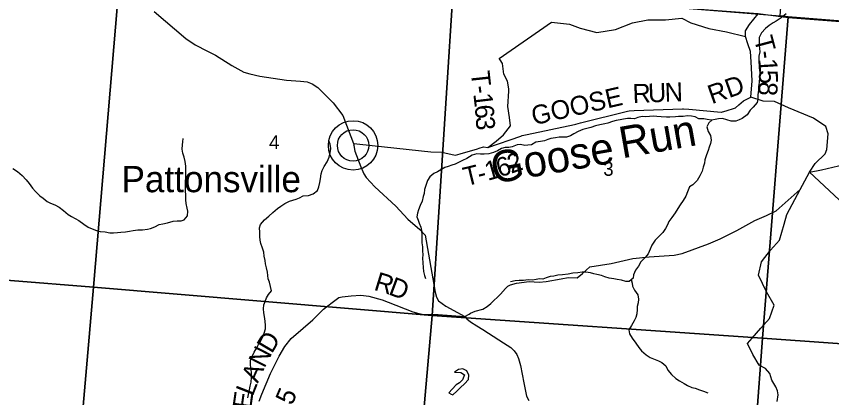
# Model space of a CAD drawing. Extents: x 0 to 42, y 0 to 22.
# Drawn here: x 6.349 to 7.577, y 19.536 to 20.11 of the extents above; entities that cross this region are included whole.
import ezdxf

# ---------------------------------------------------------------- set-up
doc = ezdxf.new("R2010")
doc.units = 0
for name, color, linetype in [('GM_X_County_Road', 7, 'Continuous'), ('GM_X_Minor_Lake', 7, 'Continuous'), ('GM_X_Minor_River', 7, 'Continuous'), ('GM_X_Minor_River_Text', 7, 'Continuous'), ('GM_X_Section', 7, 'Continuous'), ('GM_X_Section_Text', 7, 'Continuous'), ('GM_X_Township', 7, 'Continuous'), ('GM_X_Township_Road', 7, 'Continuous'), ('GM_X_Township_Road_Text', 7, 'Continuous'), ('GM_X_Unincorporated', 7, 'Continuous'), ('GM_X_Unincorporated_Location', 7, 'Continuous'), ('GM_X_Unincorporated_Text', 7, 'Continuous')]:
    doc.layers.add(name, color=color, linetype=linetype)

msp = doc.modelspace()

# ---------------------------------------------------------------- linework, layer by layer
at = {"layer": 'GM_X_County_Road'}
msp.add_lwpolyline([(6.5568, 20.1173), (6.6043, 20.0769), (6.6185, 20.0672), (6.6369, 20.0579), (6.6492, 20.0517), (6.6739, 20.0361), (6.6916, 20.026), (6.7009, 20.0236), (6.716, 20.0202), (6.7562, 20.0143), (6.777, 20.0127), (6.787, 20.0118), (6.7949, 20.0088), (6.8033, 20.003), (6.8264, 19.9801), (6.8408, 19.961), (6.8463, 19.9462), (6.857, 19.9189), (6.8591, 19.9075), (6.8678, 19.8837), (6.8727, 19.8731), (6.8759, 19.8674), (6.889, 19.8535), (6.9206, 19.8244), (6.9389, 19.8047), (6.9566, 19.7894), (6.9648, 19.7807), (6.9799, 19.6953), (6.9818, 19.6874), (6.9852, 19.6823), (6.996, 19.674), (7.0136, 19.6643), (7.0245, 19.6586), (7.0274, 19.6552), (7.0333, 19.6507), (7.0428, 19.6445), (7.0518, 19.6388), (7.06, 19.6334), (7.0828, 19.6187), (7.0938, 19.6118), (7.099, 19.6066), (7.1027, 19.6014), (7.1055, 19.5953), (7.1083, 19.585), (7.1133, 19.5587), (7.1177, 19.5388), (7.1212, 19.532)], dxfattribs=at)
at = {"layer": 'GM_X_Minor_Lake'}
for points in [[(7.0093, 19.5745), (7.0187, 19.5741), (7.024, 19.5705), (7.0211, 19.5631), (7.0164, 19.5589), (7.0115, 19.5557), (7.0056, 19.5489), (7.0003, 19.5436), (7.004, 19.5417)], [(7.004, 19.5417), (7.0063, 19.5406), (7.0124, 19.5462), (7.0183, 19.5515), (7.0242, 19.5574), (7.0299, 19.5638), (7.0306, 19.5704), (7.0278, 19.5767), (7.0214, 19.5797), (7.0151, 19.5786), (7.0093, 19.5745)]]:
    msp.add_lwpolyline(points, dxfattribs=at)
at = {"layer": 'GM_X_Minor_River'}
for points in [[(7.5084, 20.1138), (7.5012, 20.1078), (7.4936, 20.103), (7.4887, 20.1002), (7.483, 20.0962), (7.4775, 20.0919), (7.4714, 20.0853), (7.4678, 20.0783), (7.4676, 20.0734), (7.4679, 20.0667), (7.4685, 20.0616), (7.4688, 20.0569), (7.4675, 20.0502), (7.4675, 20.0434), (7.469, 20.0362), (7.4693, 20.0301), (7.4686, 20.0229), (7.4685, 20.018), (7.4676, 20.0108), (7.4666, 20.0044), (7.4666, 19.9989), (7.466, 19.992), (7.4656, 19.9854), (7.4648, 19.9805), (7.4589, 19.9735), (7.4542, 19.9688), (7.4496, 19.962), (7.4424, 19.9563), (7.4377, 19.9544), (7.4327, 19.9523), (7.4255, 19.9524), (7.4193, 19.9543), (7.4127, 19.9562), (7.4068, 19.956), (7.4017, 19.9549), (7.3962, 19.954), (7.3896, 19.9551), (7.3843, 19.9557), (7.3771, 19.9561), (7.3714, 19.959), (7.3661, 19.9601), (7.3601, 19.9603), (7.3535, 19.9594), (7.3466, 19.9592), (7.3417, 19.9587), (7.3334, 19.9583), (7.3285, 19.9583), (7.3201, 19.9587), (7.3139, 19.9595), (7.3082, 19.9597), (7.3029, 19.9592), (7.2967, 19.9588), (7.2916, 19.9592), (7.2853, 19.9577), (7.28, 19.956), (7.2747, 19.9564), (7.2694, 19.9566), (7.2635, 19.9553), (7.2586, 19.9546), (7.2527, 19.9532), (7.2471, 19.9517), (7.2402, 19.9493), (7.2355, 19.9482), (7.2281, 19.9469), (7.2215, 19.9452), (7.2143, 19.9431), (7.2084, 19.9414), (7.2023, 19.9397), (7.1953, 19.9369), (7.1889, 19.9332), (7.1838, 19.9303), (7.1777, 19.9283), (7.1718, 19.9283), (7.1667, 19.9281), (7.161, 19.9272), (7.1542, 19.9264), (7.1495, 19.9247), (7.1447, 19.9229), (7.1387, 19.9217), (7.1317, 19.9206), (7.1249, 19.917), (7.1197, 19.9163), (7.1148, 19.9159), (7.1084, 19.9171), (7.1035, 19.9169), (7.0961, 19.9137), (7.091, 19.9128), (7.0855, 19.9126)], [(7.3966, 19.954), (7.3922, 19.9498), (7.3892, 19.9439), (7.3911, 19.9371), (7.3944, 19.9307), (7.3956, 19.9238), (7.3946, 19.9189), (7.3927, 19.9134), (7.3908, 19.9085), (7.3887, 19.9017), (7.3862, 19.8941), (7.3854, 19.8894), (7.3833, 19.8831), (7.3818, 19.8774), (7.3787, 19.87), (7.3745, 19.863), (7.3679, 19.8568), (7.363, 19.8534), (7.3599, 19.846), (7.3576, 19.8396), (7.3536, 19.8332), (7.3489, 19.8265), (7.3454, 19.821), (7.3411, 19.8146), (7.3363, 19.8074), (7.3319, 19.8012), (7.3297, 19.7963), (7.327, 19.791), (7.3226, 19.7851), (7.3171, 19.7794), (7.3112, 19.7734), (7.3061, 19.766), (7.3036, 19.7596), (7.3009, 19.7529), (7.2968, 19.7476), (7.2895, 19.7405), (7.2859, 19.734), (7.2816, 19.728), (7.2787, 19.7212), (7.2779, 19.7164), (7.2722, 19.7113), (7.2671, 19.7113), (7.2605, 19.7131), (7.2541, 19.714), (7.249, 19.715), (7.242, 19.716), (7.2355, 19.7183), (7.2304, 19.7204), (7.2236, 19.7215), (7.2187, 19.7229), (7.2138, 19.7244), (7.207, 19.7252), (7.2015, 19.725), (7.1948, 19.7244), (7.1871, 19.7237), (7.1801, 19.7224), (7.1719, 19.7213), (7.1649, 19.7209), (7.1585, 19.7192), (7.153, 19.7185), (7.1473, 19.7168), (7.142, 19.7149), (7.1371, 19.7151), (7.1318, 19.7144), (7.1267, 19.7131), (7.1199, 19.7135), (7.1132, 19.7129), (7.1066, 19.7129), (7.1002, 19.712), (7.0932, 19.7107)], [(6.6046, 19.8339), (6.6043, 19.8411), (6.6039, 19.8477), (6.6039, 19.8534), (6.6041, 19.861), (6.6045, 19.868), (6.6044, 19.8727), (6.6044, 19.8801), (6.6046, 19.8849), (6.6033, 19.8917), (6.6018, 19.898), (6.5998, 19.9042), (6.599, 19.9105), (6.5992, 19.9167), (6.6002, 19.9215), (6.6006, 19.9262)], [(6.7893, 19.8406), (6.796, 19.8433), (6.8027, 19.8482), (6.8046, 19.8537), (6.8061, 19.8602), (6.8071, 19.8655), (6.8084, 19.8734), (6.8096, 19.8782), (6.8128, 19.8844), (6.8172, 19.8912), (6.8201, 19.898), (6.8218, 19.905), (6.8226, 19.9111), (6.8218, 19.9179), (6.8196, 19.9227)], [(7.0855, 19.9126), (7.0798, 19.9111), (7.0739, 19.9079), (7.0677, 19.9051), (7.0608, 19.9032), (7.0535, 19.9027), (7.0482, 19.9029), (7.0427, 19.9033), (7.0358, 19.9014), (7.0277, 19.8963), (7.0212, 19.8933), (7.0161, 19.8906), (7.0101, 19.8876), (7.0051, 19.8863), (6.9994, 19.8844), (6.9947, 19.8825), (6.9833, 19.8761), (6.978, 19.8735), (6.9721, 19.8688), (6.9685, 19.8631), (6.9657, 19.8557), (6.9638, 19.8495), (6.9632, 19.8438), (6.962, 19.8389), (6.9605, 19.8322), (6.9574, 19.8256), (6.9549, 19.8192), (6.9534, 19.814), (6.9525, 19.8087), (6.9545, 19.8036), (6.956, 19.7989), (6.9585, 19.793), (6.9594, 19.7877), (6.9597, 19.7809), (6.9599, 19.7744), (6.9601, 19.7691), (6.9608, 19.7632), (6.961, 19.7572), (6.9612, 19.7513), (6.961, 19.7464), (6.9621, 19.7321), (6.9626, 19.7263), (6.9637, 19.7204), (6.9656, 19.7156)], [(6.344, 19.8814), (6.351, 19.8768), (6.3578, 19.8707), (6.3642, 19.8641), (6.3684, 19.8587), (6.3736, 19.8515), (6.378, 19.8464), (6.3844, 19.8403), (6.3895, 19.8363), (6.3959, 19.8317), (6.4008, 19.8292), (6.407, 19.8264), (6.4138, 19.8228), (6.4203, 19.8178), (6.4272, 19.8121), (6.4323, 19.809), (6.438, 19.806), (6.4431, 19.8031), (6.451, 19.7976), (6.4576, 19.793), (6.4633, 19.7902), (6.4701, 19.7881), (6.4756, 19.7863), (6.483, 19.7857), (6.49, 19.7842), (6.4953, 19.7842), (6.5015, 19.7849), (6.5068, 19.7855), (6.5136, 19.786), (6.5195, 19.7871), (6.525, 19.7879), (6.5322, 19.7888), (6.5392, 19.7891), (6.5466, 19.7899), (6.5515, 19.791), (6.5577, 19.7933), (6.5642, 19.797), (6.5697, 19.7981), (6.5771, 19.7994), (6.5854, 19.8017), (6.5913, 19.8024), (6.5975, 19.8024), (6.6022, 19.8041), (6.607, 19.81), (6.6074, 19.8168), (6.6063, 19.8217), (6.6048, 19.8287), (6.6046, 19.8339)], [(6.6978, 19.5359), (6.6988, 19.5413), (6.7003, 19.5482), (6.7011, 19.5539), (6.7028, 19.5597), (6.7034, 19.5667), (6.7033, 19.5732), (6.7027, 19.5793), (6.7016, 19.5851), (6.702, 19.5922), (6.7047, 19.5995), (6.7073, 19.6048), (6.7115, 19.6115), (6.7138, 19.6164), (6.7178, 19.623), (6.7205, 19.6283), (6.7226, 19.6332), (6.7243, 19.6401), (6.7243, 19.6448), (6.724, 19.6514), (6.723, 19.6586), (6.7221, 19.6638), (6.7216, 19.67), (6.722, 19.6759), (6.7237, 19.681), (6.7258, 19.6867), (6.7292, 19.6918), (6.7336, 19.6971), (6.7321, 19.7037), (6.7304, 19.7102), (6.7283, 19.7153), (6.7278, 19.7204), (6.7274, 19.7254), (6.7259, 19.7316), (6.7246, 19.7379), (6.7239, 19.7426), (6.7224, 19.7493), (6.7217, 19.7555), (6.7198, 19.7614), (6.7174, 19.7684), (6.7166, 19.7732), (6.7161, 19.7789), (6.7157, 19.7855), (6.7156, 19.7918), (6.7171, 19.7971), (6.723, 19.8041), (6.7296, 19.8096), (6.7355, 19.8148), (6.7427, 19.8211), (6.7475, 19.8245), (6.7535, 19.8286), (6.7605, 19.8318), (6.7655, 19.8337), (6.7706, 19.835), (6.7757, 19.8371), (6.781, 19.8399), (6.7893, 19.8406)], [(7.2753, 19.7141), (7.2766, 19.7088), (7.2773, 19.7039), (7.2799, 19.698), (7.2852, 19.6912), (7.2861, 19.6846), (7.2854, 19.6789), (7.284, 19.6736), (7.2842, 19.6688), (7.2838, 19.6626), (7.2823, 19.6569), (7.2794, 19.6518), (7.2758, 19.645), (7.2718, 19.6385), (7.2724, 19.6323), (7.2767, 19.6258), (7.282, 19.6186), (7.2867, 19.6116), (7.2908, 19.6068), (7.2978, 19.6009), (7.3039, 19.5969), (7.3088, 19.5946), (7.3163, 19.5916), (7.3214, 19.5895), (7.3273, 19.584), (7.3301, 19.5775), (7.3356, 19.5712), (7.3424, 19.5654), (7.348, 19.5617), (7.3548, 19.5575), (7.3599, 19.5545), (7.3666, 19.5518), (7.3715, 19.5507), (7.3781, 19.548), (7.3839, 19.5459), (7.3906, 19.5434)]]:
    msp.add_lwpolyline(points, dxfattribs=at)
at = {"layer": 'GM_X_Section'}
for points in [[(7.5385, 20.6135), (8.0546, 20.576), (8.0131, 20.0691), (7.5113, 20.1095), (7.4997, 20.1108)], [(6.0085, 20.238), (6.4512, 20.1989), (6.5071, 20.1953), (6.4653, 19.7024), (5.9652, 19.7427)], [(6.5071, 20.1953), (6.9833, 20.1533), (7.0068, 20.151), (6.9755, 19.66), (6.4653, 19.7024)], [(7.4997, 20.1108), (7.5113, 20.1095), (7.4728, 19.6259), (6.9755, 19.66), (7.0068, 20.151)], [(7.5113, 20.1095), (8.0131, 20.0691), (8.0207, 20.0684), (7.9742, 19.5901), (7.4728, 19.6259)], [(5.9652, 19.7427), (6.4653, 19.7024), (6.4215, 19.1942), (5.9249, 19.2362)], [(6.4653, 19.7024), (6.9755, 19.66), (6.9308, 19.1519), (6.4215, 19.1942)], [(7.4728, 19.6259), (7.4347, 19.1125), (6.9308, 19.1519), (6.9755, 19.66)], [(7.4728, 19.6259), (7.9742, 19.5901), (7.9439, 19.075), (7.4347, 19.1125)]]:
    msp.add_lwpolyline(points, close=True, dxfattribs=at)
at = {"layer": 'GM_X_Township'}
msp.add_lwpolyline([(6.3062, 20.211), (6.4486, 20.1964), (6.4625, 20.1954), (6.5052, 20.1923), (6.9777, 20.151), (7.4661, 20.1144), (7.5116, 20.1083), (8.1585, 20.0585), (8.5294, 20.0335), (8.4853, 19.4313)], dxfattribs=at)
at = {"layer": 'GM_X_Township_Road'}
msp.add_lwpolyline([(8.604, 20.9), (5.4466, 20.9), (5.4327, 20.7492), (5.4317, 20.7371), (5.4312, 20.7306), (5.4298, 20.7203), (5.4281, 20.716), (5.4083, 20.5211), (5.3882, 20.287), (5.7544, 20.2607), (6.2569, 20.215), (6.3062, 20.211), (6.4486, 20.1964), (6.4625, 20.1954), (6.5052, 20.1923), (6.9777, 20.151), (7.4661, 20.1144), (7.5116, 20.1083), (8.1585, 20.0585), (8.5294, 20.0335), (8.5516, 20.2479), (8.5706, 20.4739), (8.6039, 20.8987)], close=True, dxfattribs=at)
for points in [[(7.4551, 19.9884), (7.4574, 20.013), (7.4557, 20.0418), (7.4548, 20.0572), (7.4506, 20.069), (7.4474, 20.0799), (7.4474, 20.0885), (7.4535, 20.0981), (7.4662, 20.1141), (7.4669, 20.1149)], [(7.0777, 20.0445), (7.0764, 20.0466), (7.1552, 20.1016), (7.1824, 20.0985), (7.1982, 20.0923), (7.2232, 20.086), (7.2515, 20.0902), (7.2771, 20.1006), (7.3, 20.1047), (7.327, 20.1047), (7.3512, 20.1075), (7.365, 20.1006), (7.392, 20.0916), (7.4187, 20.0866), (7.4474, 20.0799)], [(7.0909, 19.9974), (7.0911, 20.0009), (7.0887, 20.0126), (7.0835, 20.023), (7.0811, 20.0392), (7.0777, 20.0445)], [(7.059, 19.913), (7.0718, 19.9223), (7.0828, 19.9316), (7.0935, 19.9454), (7.0921, 19.9578), (7.0894, 19.9747), (7.0909, 19.9974)], [(7.0462, 19.9118), (7.0528, 19.9138), (7.059, 19.913), (7.1088, 19.93), (7.1107, 19.9306), (7.1183, 19.9322), (7.1896, 19.9476), (7.1918, 19.948), (7.199, 19.9498), (7.2698, 19.9674), (7.2722, 19.968), (7.2795, 19.9683), (7.3524, 19.9712), (7.3541, 19.9712), (7.362, 19.9705), (7.4105, 19.966), (7.4111, 19.9659), (7.4197, 19.9687), (7.429, 19.9717), (7.432, 19.9727), (7.437, 19.9769), (7.4445, 19.9831), (7.4551, 19.9884)], [(7.7314, 19.7005), (7.5437, 19.8759), (7.5523, 19.8886), (7.567, 19.903), (7.5696, 19.9099), (7.5716, 19.9332), (7.5681, 19.9444), (7.5498, 19.9571), (7.5122, 19.9723), (7.4909, 19.9819), (7.4737, 19.9824), (7.4551, 19.9884)], [(6.857, 19.9189), (6.8618, 19.9182), (6.9593, 19.908), (6.9735, 19.9065), (6.9901, 19.9057), (7.0055, 19.9021), (7.0106, 19.9013), (7.0174, 19.9033), (7.0435, 19.911), (7.0462, 19.9118)], [(7.2016, 19.7234), (7.2129, 19.7333), (7.2452, 19.7382), (7.2775, 19.7457), (7.3023, 19.7482), (7.3396, 19.7507), (7.352, 19.7531), (7.3917, 19.768), (7.4091, 19.7755), (7.434, 19.7879), (7.4613, 19.8028), (7.4787, 19.8103), (7.4936, 19.8177), (7.5297, 19.8497), (7.5437, 19.8759), (7.5619, 19.8792), (7.6043, 19.889)], [(7.4952, 19.5306), (7.4965, 19.5404), (7.4955, 19.5467), (7.4929, 19.5524), (7.487, 19.5629), (7.4841, 19.5726), (7.4774, 19.5802), (7.4677, 19.5851), (7.4581, 19.6012), (7.4505, 19.6178), (7.4575, 19.6258), (7.4704, 19.6407), (7.4833, 19.6556), (7.4905, 19.6756), (7.479, 19.6956), (7.4669, 19.7206), (7.4712, 19.7406), (7.4847, 19.7584), (7.4983, 19.7734), (7.5054, 19.7975), (7.5097, 19.8119), (7.5297, 19.8497)], [(7.031, 19.6622), (7.0332, 19.6635), (7.0403, 19.6663), (7.0516, 19.6696), (7.0582, 19.6734), (7.064, 19.6782), (7.0785, 19.6919), (7.0858, 19.7008), (7.0894, 19.7042), (7.0934, 19.7063), (7.1024, 19.7084), (7.1213, 19.7109), (7.1365, 19.7102), (7.147, 19.7113), (7.1695, 19.7152), (7.1802, 19.717), (7.1938, 19.7165), (7.2016, 19.7234)], [(6.715, 19.5311), (6.7187, 19.5417), (6.7321, 19.5729), (6.7452, 19.5989), (6.7535, 19.6135), (6.7633, 19.6256), (6.7812, 19.6407), (6.7959, 19.6535), (6.8118, 19.6695), (6.8247, 19.6793), (6.835, 19.6872), (6.84, 19.6883), (6.8534, 19.6896), (6.8678, 19.6905), (6.88, 19.6891), (6.9001, 19.6834), (6.9091, 19.6801), (6.9461, 19.6655), (6.9554, 19.6631), (6.9627, 19.6617), (6.9844, 19.6617), (7.0245, 19.6586), (7.031, 19.6622)]]:
    msp.add_lwpolyline(points, dxfattribs=at)
at = {"layer": 'GM_X_Unincorporated'}
for radius in [0.0372, 0.0236]:
    msp.add_circle((6.8563, 19.9159), radius, dxfattribs=at)
at = {"layer": 'GM_X_Unincorporated_Location'}
msp.add_line((6.8563, 19.9159), (6.8563, 19.9159), dxfattribs=at)

# ---------------------------------------------------------------- texts
at = {"layer": 'GM_X_Minor_River_Text'}
for s, rotation, p in [('Run', 9.9985, (7.2614, 19.8963)), ('Goose', 9.9991, (7.0682, 19.858))]:
    msp.add_text(s, height=0.04735, rotation=rotation, dxfattribs=at).set_placement(p)
at = {"layer": 'GM_X_Section_Text'}
for s, p in [('4', (6.7298, 19.9103)), ('3', (7.2331, 19.8702))]:
    msp.add_text(s, height=0.0209, rotation=0, dxfattribs=at).set_placement(p)
at = {"layer": 'GM_X_Township_Road_Text'}
for s, height, rotation, p in [('T', 0.0284, 284.7684, (7.4597, 20.0767)), ('-', 0.0284, 277.4344, (7.4649, 20.0572)), ('1', 0.0284, 273.4825, (7.4664, 20.0462)), ('T', 0.0284, 276.1102, (7.0335, 20.0266)), ('5', 0.0284, 271.3624, (7.4674, 20.0292)), ('RD', 0.02841, 19.4122, (7.3965, 19.9778)), ('-', 0.0284, 277.3025, (7.0358, 20.0048)), ('GOOSE', 0.02841, 12.9027, (7.1284, 19.9461)), ('R', 0.0284, 2.2018, (7.2777, 19.9796)), ('U', 0.0284, 2.2008, (7.301, 19.9805)), ('N', 0.0284, 1.9164, (7.326, 19.9815)), ('8', 0.0284, 266.1374, (7.4678, 20.0125)), ('1', 0.0284, 276.8126, (7.0373, 19.9933)), ('6', 0.0284, 275.1954, (7.0394, 19.9761)), ('3', 0.0284, 273.9006, (7.0409, 19.9589)), ('2', 0.0284, 19.0902, (7.0943, 19.8732)), ('1', 0.0284, 15.8742, (7.0591, 19.8625)), ('6', 0.0284, 17.6825, (7.0769, 19.8676)), ('T', 0.0284, 13.7296, (7.026, 19.8543)), ('-', 0.0284, 14.3745, (7.047, 19.8594)), ('R', 0.0284, 342.8611, (6.8863, 19.6989)), ('D', 0.0284, 339.3838, (6.9082, 19.6922)), ('D', 0.0284, 59.2836, (6.734, 19.6015)), ('N', 0.0284, 62.8762, (6.7228, 19.5796)), ('A', 0.0284, 66.2413, (6.7129, 19.5571)), ('L', 0.0284, 68.536, (6.7053, 19.5376)), ('5', 0.0284, 66.921, (6.7644, 19.5235)), ('E', 0.0284, 82.0023, (6.7028, 19.5183))]:
    msp.add_text(s, height=height, rotation=rotation, dxfattribs=at).set_placement(p)
at = {"layer": 'GM_X_Unincorporated_Text'}
msp.add_text('Pattonsville', height=0.039489, rotation=0, dxfattribs=at).set_placement((6.5077, 19.8455))

doc.saveas('drawing.dxf')
